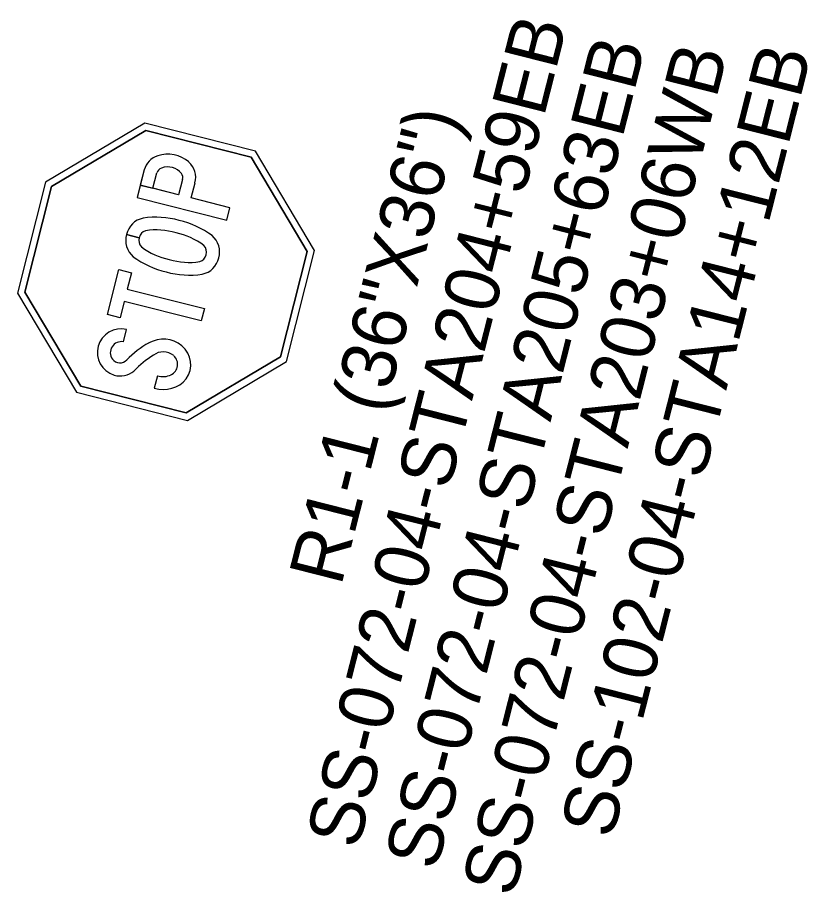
# Model space of a CAD drawing. Extents: x 670257 to 671518, y 737783 to 738188.
# Drawn here: x 670276.607 to 670280.256, y 738133.27 to 738137.305 of the extents above; entities that cross this region are included whole.
import ezdxf

# ---------------------------------------------------------------- set-up
doc = ezdxf.new("R2010")
doc.units = 0
doc.layers.add('Default', color=7, linetype='Continuous')

msp = doc.modelspace()

# ---------------------------------------------------------------- linework, layer by layer
at = {"layer": 'Default'}
for p, q in [((670277.1687, 738136.2897), (670277.1105, 738136.3044)), ((670277.1105, 738136.3044), (670277.1687, 738136.2897)), ((670277.1687, 738136.2897), (670277.1105, 738136.3044)), ((670277.1105, 738136.3044), (670277.1687, 738136.2897)), ((670277.0962, 738135.8094), (670277.1106, 738135.8661)), ((670277.0962, 738135.8094), (670277.1106, 738135.8661)), ((670277.0962, 738135.8094), (670277.1106, 738135.8661)), ((670277.2527, 738135.6526), (670277.2381, 738135.5951)), ((670277.2527, 738135.6526), (670277.2381, 738135.5951)), ((670277.2527, 738135.6526), (670277.2381, 738135.5951))]:
    msp.add_line(p, q, dxfattribs=at)
for points in [[(670277.9776, 738136.2311), (670277.7056, 738136.688), (670277.1938, 738136.8178), (670276.7369, 738136.5458), (670276.6071, 738136.034), (670276.8791, 738135.5771), (670277.3909, 738135.4473), (670277.8478, 738135.7193)], [(670277.9433, 738136.2261), (670277.6848, 738136.6603), (670277.1988, 738136.7835), (670276.7646, 738136.5251), (670276.6413, 738136.039), (670276.8998, 738135.6049), (670277.3859, 738135.4816), (670277.82, 738135.74)], [(670277.0992, 738135.9959), (670277.0801, 738135.9205), (670277.0221, 738135.9352), (670277.0748, 738136.143), (670277.1328, 738136.1283), (670277.1136, 738136.0529), (670277.4695, 738135.9627), (670277.455, 738135.9056)], [(670277.0992, 738135.9959), (670277.0801, 738135.9205), (670277.0221, 738135.9352), (670277.0748, 738136.143), (670277.1328, 738136.1283), (670277.1136, 738136.0529), (670277.4695, 738135.9627), (670277.455, 738135.9056)], [(670277.0992, 738135.9959), (670277.0801, 738135.9205), (670277.0221, 738135.9352), (670277.0748, 738136.143), (670277.1328, 738136.1283), (670277.1136, 738136.0529), (670277.4695, 738135.9627), (670277.455, 738135.9056)]]:
    msp.add_lwpolyline(points, close=True, dxfattribs=at)
for points in [[(670277.9776, 738136.2311), (670277.7056, 738136.688), (670277.1938, 738136.8178), (670276.7369, 738136.5458), (670276.6071, 738136.034), (670276.8791, 738135.5771), (670277.3909, 738135.4473), (670277.8478, 738135.7193), (670277.9776, 738136.2311)], [(670277.82, 738135.74), (670277.3859, 738135.4816), (670276.8998, 738135.6049), (670276.6413, 738136.039), (670276.7646, 738136.5251), (670277.1988, 738136.7835), (670277.6848, 738136.6603), (670277.9433, 738136.2261), (670277.82, 738135.74)], [(670277.1914, 738136.6027), (670277.1591, 738136.4754), (670277.5729, 738136.3704), (670277.5873, 738136.4275), (670277.4082, 738136.4729), (670277.4261, 738136.5432)], [(670277.1914, 738136.6027), (670277.1736, 738136.5325), (670277.2315, 738136.5178), (670277.2494, 738136.588)], [(670277.1914, 738136.6027), (670277.1736, 738136.5325), (670277.2315, 738136.5178), (670277.2494, 738136.588)], [(670277.3681, 738136.5579), (670277.3503, 738136.4876), (670277.2315, 738136.5177), (670277.2494, 738136.588)], [(670277.1736, 738136.5324), (670277.1591, 738136.4754), (670277.5729, 738136.3704), (670277.5873, 738136.4275), (670277.4082, 738136.4729), (670277.4261, 738136.5432)], [(670277.1736, 738136.5324), (670277.1591, 738136.4754), (670277.5729, 738136.3704), (670277.5873, 738136.4275), (670277.4082, 738136.4729), (670277.4261, 738136.5432)], [(670277.3681, 738136.5579), (670277.3503, 738136.4876), (670277.1736, 738136.5324)], [(670277.3681, 738136.5579), (670277.3503, 738136.4876), (670277.1736, 738136.5324)]]:
    msp.add_lwpolyline(points, dxfattribs=at)
for centre, major_axis, start_param, end_param in [((670277.2841, 738136.577), (-0.0932, 0.0236), 5.276851, 6.259896), ((670277.2841, 738136.577), (-0.0932, 0.0236), 5.276851, 6.259896), ((670277.2841, 738136.577), (-0.0932, 0.0236), 5.276851, 6.259896), ((670277.3021, 738136.5343), (-0.1385, 0.0351), 4.228611, 5.30173), ((670277.3021, 738136.5343), (-0.1385, 0.0351), 4.228611, 5.30173), ((670277.3021, 738136.5343), (-0.1385, 0.0351), 4.228611, 5.30173), ((670277.301, 738136.5371), (-0.0776, 0.0197), 4.048017, 5.334419), ((670277.301, 738136.5371), (-0.0776, 0.0197), 4.048017, 5.334419), ((670277.301, 738136.5371), (-0.0776, 0.0197), 4.048017, 5.334419), ((670277.3327, 738136.5682), (-0.0936, 0.0238), 3.128753, 4.226983), ((670277.3327, 738136.5682), (-0.0936, 0.0238), 3.128753, 4.226983), ((670277.3327, 738136.5682), (-0.0936, 0.0238), 3.128753, 4.226983), ((670277.2863, 738136.5747), (-0.0381, 0.0097), 5.344449, 6.183368), ((670277.2863, 738136.5747), (-0.0381, 0.0097), 5.344449, 6.183368), ((670277.2863, 738136.5747), (-0.0381, 0.0097), 5.344449, 6.183368), ((670277.3376, 738136.5676), (-0.0311, 0.0079), 3.082992, 3.98323), ((670277.3376, 738136.5676), (-0.0311, 0.0079), 3.082992, 3.98323), ((670277.3376, 738136.5676), (-0.0311, 0.0079), 3.082992, 3.98323), ((670277.2475, 738135.9851), (-0.3923, 0.0995), 4.692766, 5.109028), ((670277.2475, 738135.9851), (-0.3923, 0.0995), 4.692766, 5.109028), ((670277.2475, 738135.9851), (-0.3923, 0.0995), 4.692766, 5.109028), ((670277.2087, 738136.2831), (-0.0975, 0.0247), 5.182411, 6.318105), ((670277.2087, 738136.2831), (-0.0975, 0.0247), 5.182411, 6.317893), ((670277.2087, 738136.2831), (-0.0975, 0.0247), 5.182411, 6.317893), ((670277.2629, 738135.9812), (-0.3923, 0.0995), 4.31575, 4.732012), ((670277.2629, 738135.9812), (-0.3923, 0.0995), 4.31575, 4.732012), ((670277.2629, 738135.9812), (-0.3923, 0.0995), 4.31575, 4.732012), ((670277.207, 738136.2764), (-0.0975, 0.0247), 6.248265, 7.383959), ((670277.207, 738136.2764), (-0.0975, 0.0247), 6.248265, 7.383959), ((670277.207, 738136.2764), (-0.0975, 0.0247), 6.248265, 7.383959), ((670277.2109, 738136.2813), (-0.0417, 0.0106), 5.258281, 6.33678), ((670277.2109, 738136.2813), (-0.0417, 0.0106), 5.258281, 6.336283), ((670277.2109, 738136.2813), (-0.0417, 0.0106), 5.258281, 6.336283), ((670277.2476, 738136.012), (-0.3082, 0.0782), 4.667051, 5.113562), ((670277.2476, 738136.012), (-0.3082, 0.0782), 4.667051, 5.113562), ((670277.2476, 738136.012), (-0.3082, 0.0782), 4.667051, 5.113562), ((670277.2756, 738136.0049), (-0.3082, 0.0782), 4.311216, 4.757727), ((670277.2756, 738136.0049), (-0.3082, 0.0782), 4.311216, 4.757727), ((670277.2756, 738136.0049), (-0.3082, 0.0782), 4.311216, 4.757727), ((670277.2098, 738136.2769), (-0.0417, 0.0106), 6.22959, 7.30809), ((670277.2098, 738136.2769), (-0.0417, 0.0106), 6.22959, 7.30809), ((670277.2098, 738136.2769), (-0.0417, 0.0106), 6.22959, 7.30809), ((670277.439, 738136.2247), (-0.0975, 0.0247), 3.106673, 4.242367), ((670277.439, 738136.2247), (-0.0975, 0.0247), 3.106673, 4.242367), ((670277.439, 738136.2247), (-0.0975, 0.0247), 3.106673, 4.242367), ((670277.3704, 738136.4961), (-0.3082, 0.0782), 1.169623, 1.616135), ((670277.3704, 738136.4961), (-0.3082, 0.0782), 1.169623, 1.616135), ((670277.3704, 738136.4961), (-0.3082, 0.0782), 1.169623, 1.616135), ((670277.4362, 738136.2241), (-0.0417, 0.0106), 3.087997, 4.166497), ((670277.4362, 738136.2241), (-0.0417, 0.0106), 3.087997, 4.166497), ((670277.4362, 738136.2241), (-0.0417, 0.0106), 3.087997, 4.166497), ((670277.3831, 738136.5199), (-0.3923, 0.0995), 1.174158, 1.59042), ((670277.3831, 738136.5199), (-0.3923, 0.0995), 1.174158, 1.59042), ((670277.3831, 738136.5199), (-0.3923, 0.0995), 1.174158, 1.59042), ((670277.3984, 738136.489), (-0.3082, 0.0782), 1.525458, 1.97197), ((670277.3984, 738136.489), (-0.3082, 0.0782), 1.525458, 1.97197), ((670277.3984, 738136.489), (-0.3082, 0.0782), 1.525458, 1.97197), ((670277.4351, 738136.2197), (-0.0417, 0.0106), 2.116688, 3.195188), ((670277.4351, 738136.2197), (-0.0417, 0.0106), 2.116688, 3.195188), ((670277.4351, 738136.2197), (-0.0417, 0.0106), 2.116688, 3.195188), ((670277.4373, 738136.218), (-0.0975, 0.0247), 2.040819, 3.176513), ((670277.4373, 738136.218), (-0.0975, 0.0247), 2.040819, 3.176513), ((670277.4373, 738136.218), (-0.0975, 0.0247), 2.040819, 3.176513), ((670277.3985, 738136.5159), (-0.3923, 0.0995), 1.551173, 1.967435), ((670277.3985, 738136.5159), (-0.3923, 0.0995), 1.551173, 1.967435), ((670277.3985, 738136.5159), (-0.3923, 0.0995), 1.551173, 1.967435), ((670277.0863, 738135.7598), (-0.1074, 0.0272), 4.736267, 7.790596), ((670277.0863, 738135.7598), (-0.1074, 0.0272), 4.736267, 7.790596), ((670277.0863, 738135.7598), (-0.1074, 0.0272), 4.736267, 7.790596), ((670277.2805, 738135.6913), (-0.1283, 0.0325), 4.260987, 5.485755), ((670277.2805, 738135.6913), (-0.1283, 0.0325), 4.260987, 5.485755), ((670277.2805, 738135.6913), (-0.1283, 0.0325), 4.260987, 5.485755), ((670277.0874, 738135.7589), (-0.0505, 0.0128), 4.786904, 7.140738), ((670277.0874, 738135.7589), (-0.0505, 0.0128), 4.786904, 7.140738), ((670277.0874, 738135.7589), (-0.0505, 0.0128), 4.786904, 7.140738), ((670277.4121, 738135.4499), (-0.397, 0.1007), 5.462886, 5.782242), ((670277.4121, 738135.4499), (-0.397, 0.1007), 5.462886, 5.782242), ((670277.4121, 738135.4499), (-0.397, 0.1007), 5.462886, 5.782242), ((670277.2901, 738135.7042), (-0.1126, 0.0286), 2.786047, 4.251692), ((670277.2901, 738135.7042), (-0.1126, 0.0286), 2.786047, 4.251692), ((670277.2901, 738135.7042), (-0.1126, 0.0286), 2.786047, 4.251692), ((670277.4628, 738135.3844), (-0.4191, 0.1063), 5.515137, 5.786988), ((670277.4628, 738135.3844), (-0.4191, 0.1063), 5.515137, 5.786988), ((670277.4628, 738135.3844), (-0.4191, 0.1063), 5.515137, 5.786988), ((670277.2802, 738135.6904), (-0.0716, 0.0182), 4.254409, 5.632398), ((670277.2802, 738135.6904), (-0.0716, 0.0182), 4.254409, 5.632398), ((670277.2802, 738135.6904), (-0.0716, 0.0182), 4.254409, 5.632398), ((670277.2919, 738135.7059), (-0.0525, 0.0133), 2.261787, 4.23006), ((670277.2919, 738135.7059), (-0.0525, 0.0133), 2.261787, 4.23006), ((670277.2919, 738135.7059), (-0.0525, 0.0133), 2.261787, 4.23006), ((670277.0795, 738135.7544), (-0.0416, 0.0106), 0.87378, 2.656959), ((670277.0795, 738135.7544), (-0.0416, 0.0106), 0.87378, 2.656959), ((670277.0795, 738135.7544), (-0.0416, 0.0106), 0.87378, 2.656959), ((670277.0803, 738135.75), (-0.0964, 0.0244), 1.534831, 2.511766), ((670277.0803, 738135.75), (-0.0964, 0.0244), 1.534831, 2.511766), ((670277.0803, 738135.75), (-0.0964, 0.0244), 1.534831, 2.511766), ((670277.2771, 738135.7327), (-0.0824, 0.0209), 1.524757, 2.28214), ((670277.2771, 738135.7327), (-0.0824, 0.0209), 1.524757, 2.28214), ((670277.2771, 738135.7327), (-0.0824, 0.0209), 1.524757, 2.28214), ((670277.2779, 738135.7266), (-0.1352, 0.0343), 1.526364, 2.701682), ((670277.2779, 738135.7266), (-0.1352, 0.0343), 1.526364, 2.701682), ((670277.2779, 738135.7266), (-0.1352, 0.0343), 1.526364, 2.701682)]:
    msp.add_ellipse(centre, major_axis=major_axis, ratio=0.984611, start_param=start_param, end_param=end_param, dxfattribs=at)

# ---------------------------------------------------------------- texts
for s, p in [('SS-072-04-STA204+59EB', (670278.1784, 738133.4637)), ('SS-072-04-STA205+63EB', (670278.5404, 738133.3658)), ('SS-072-04-STA203+06WB', (670278.8962, 738133.2431)), ('SS-102-04-STA14+12EB', (670279.3512, 738133.5115)), ('R1-1 (36"X36")', (670278.0997, 738134.6788))]:
    msp.add_text(s, height=0.25, rotation=75.7686, dxfattribs=at).set_placement(p)

doc.saveas('drawing.dxf')
